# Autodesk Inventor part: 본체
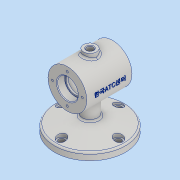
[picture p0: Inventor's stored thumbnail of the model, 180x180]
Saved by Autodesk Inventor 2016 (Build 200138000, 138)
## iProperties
Created: 2018-12
Part Number: 본체
Material: 알루미늄 6061
Document SubType Name: Modeling
Designer: 605-12
Mass: 685.082 g
Surface Area: 555.474 cm^2
Volume: 253.734 cm^3
Density: 2.7 g/cm^3
Appearance: 알루미늄 - 평지
Author: 605-12
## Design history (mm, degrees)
sketch "스케치1"
  geometry: L1 (-35, 0)-(35, 0); L2 (-35, 0)-(-35, 30); L3 (-35, 30)-(35, 30); L4 (35, 30)-(35, 0); L5 (-35, 16)-(-23, 16); L6 (-23, 16)-(-23, 14); L7 (-23, 14)-(-20, 14); L8 (-20, 14)-(-20, 25); L9 (-20, 25)-(20, 25); L10 (20, 25)-(20, 14); L11 (20, 14)-(23, 14); L12 (23, 14)-(23, 16); L13 (23, 16)-(35, 16); 2 further points
  constraints: 26 end point, 8 perpendicular, 6 point on line, 2 horizontal, 1 coincident, 1 collinear, 1 midpoint, 1 vertical
  dimensions: "d0" = 60 diameter of L3 L1; "d1" = 70 distance between parallel lines of L4 L2; "d2" = 32 diameter of L5 L1; "d3" = 28 diameter of L7 L1; "d4" = 50 diameter of L9 L1; "d5" = 12 distance of L5.start L5.end; "d6" = 3 distance of L6.end L7.end; "d7" = 40 distance of L8.end L9.end
revolve "회전1" sketch "스케치1" stored, may be unused: angle "d8" = 90 deg
node "작업 평면1"
sketch "스케치3"
  geometry: L1 (0, 0)-(0, 23); C1 r 30 at (0, 0) reference; 3 further points
  constraints: 2 coincident, 2 end point, 1 vertical, 1 vertical alignment, 2 other
  dimensions: "d13" = 23 distance of L1.start L1.end
hole "구멍1" sketch "스케치3" at (0, 23) diameter "d14" = 3.242; stored, may be unused: countersink angle "d18" = 90 deg, drill point angle "d20" = 118 deg; dims "d15" = 8, "d16" = 4, "d17" = 2, "d19" = 10
node "작업 평면2"
sketch "스케치4"
  geometry: L1 (35, 30)-(35, -30) reference; L2 (-35, 30)-(-35, -30) reference; C1 r 10 at (0, 0); 1 further point
  constraints: 1 centre point, 1 coincident
  dimensions: "d25" = 20 diameter of C1
extrude "돌출2" join sketch "스케치4" stored distance "d26" = 11; taper "d27" = 0 deg
hole "구멍2" diameter "d30" = 10; stored, may be unused: countersink angle "d34" = 90 deg, drill point angle "d36" = 118 deg; dims "d28" = 10, "d29" = 10, "d31" = 10, "d32" = 4, "d33" = 2, "d35" = 10
node "작업 평면3"
sketch "스케치6"
  geometry: C1 r 55 at (0, 0); 1 further point
  constraints: 1 centre point, 1 coincident
  dimensions: "d40" = 110 diameter of C1
extrude "돌출3" join sketch "스케치6" distance "d41" = 11; taper "d42" = 0 deg
sketch "스케치8"
  geometry: L1 (37, -10)-(28.284, -10) reference; L2 (28.284, 10)-(37, 10) reference; L3 (37, 10)-(37, 5) reference; L4 (37, 5)-(24.495, 5) reference; L5 (24.495, -5)-(37, -5) reference; L6 (37, -5)-(37, -10) reference; L7 (-75, 55)-(-64, 55) reference; L8 (-64, 55)-(-64, -55) reference; L9 (-64, -55)-(-75, -55) reference; L10 (-75, -55)-(-75, 55) reference; L11 (-27.495, -12)-(-52.478, -12); L12 (-52.478, -12)-(-64, -55); L13 (-30, 0)-(-64, 0); A1 r 30 centre (0, 0) between (28.284, 10) and (28.284, -10) reference; A2 r 25 centre (0, 0) between (24.495, 5) and (24.495, -5) reference; 1 further point
  constraints: 6 end point, 2 point on circle, 1 horizontal, 1 midpoint
  dimensions: "d51" = 12 distance between parallel lines of L13 L11; "d52" = 75 deg angle of L12 L9
revolve "회전2" sketch "스케치8" stored, may be unused: angle "d53" = 90 deg
sketch "스케치9" dims "d54" = 88
  geometry: L1 (0, 0)-(0, -44); C1 r 55 at (0, 0) reference; 2 further points
  constraints: 2 coincident, 2 end point, 1 vertical, 1 vertical alignment, 2 other
hole "구멍4" sketch "스케치9" at (0, -44) diameter "d55" = 9; stored, may be unused: countersink angle "d59" = 90 deg, drill point angle "d61" = 118 deg; dims "d56" = 10, "d57" = 14, "d58" = 1, "d60" = 4
node "작업 평면4"
sketch "스케치10"
  geometry: L1 (0, 0)-(0, -44); C1 r 7 at (0, -44); 2 further points
  constraints: 3 coincident, 2 end point, 1 centre point, 1 vertical, 1 vertical alignment, 2 other
  dimensions: "d63" = 44 distance of L1.start L1.end; "d64" = 14 diameter of C1
extrude "돌출4" cut sketch "스케치10" stored distance "d65" = 11; taper "d66" = 0 deg
fillet "모깎기1" dims "d70" = 3
fillet "모깎기2" dims "d71" = 3, "d72" = 0.3
chamfer "모따기1" distance "d73" = 1; stored, may be unused: second distance "d74" = 2, angle "d75" = 45 deg
chamfer "모따기2" distance "d76" = 1; stored, may be unused: second distance "d77" = 2, angle "d78" = 45 deg
node "작업 평면5"
sketch "스케치11"
  geometry: L1 (35, 30)-(-35, 30) reference; L2 (-35, 30)-(-35, -30) reference; L3 (35, 30)-(-35, 30) reference; L4 (-34, -16)-(-34, 16) reference; 2 further points
  constraints: 1 other
  dimensions: "d79" = 30 distance from line of point (1, 0) L1; "d80" = 35 distance from line of point (1, 0) L4
feature "엠보싱1" sketch "스케치11" dims "d13" = 23, "d81" = 0.5, "d82" = 0
node "솔리드1"
pattern_circular "원형 패턴1" dims angle "d22" = 360 deg
mirror "대칭1"
pattern_circular "원형 패턴2" dims angle "d68" = 360 deg
node "투영된 루프1"
node "절단 모서리 투영1"
other parameters: "d9" = -75, "d24" = 37, "d39" = -75
